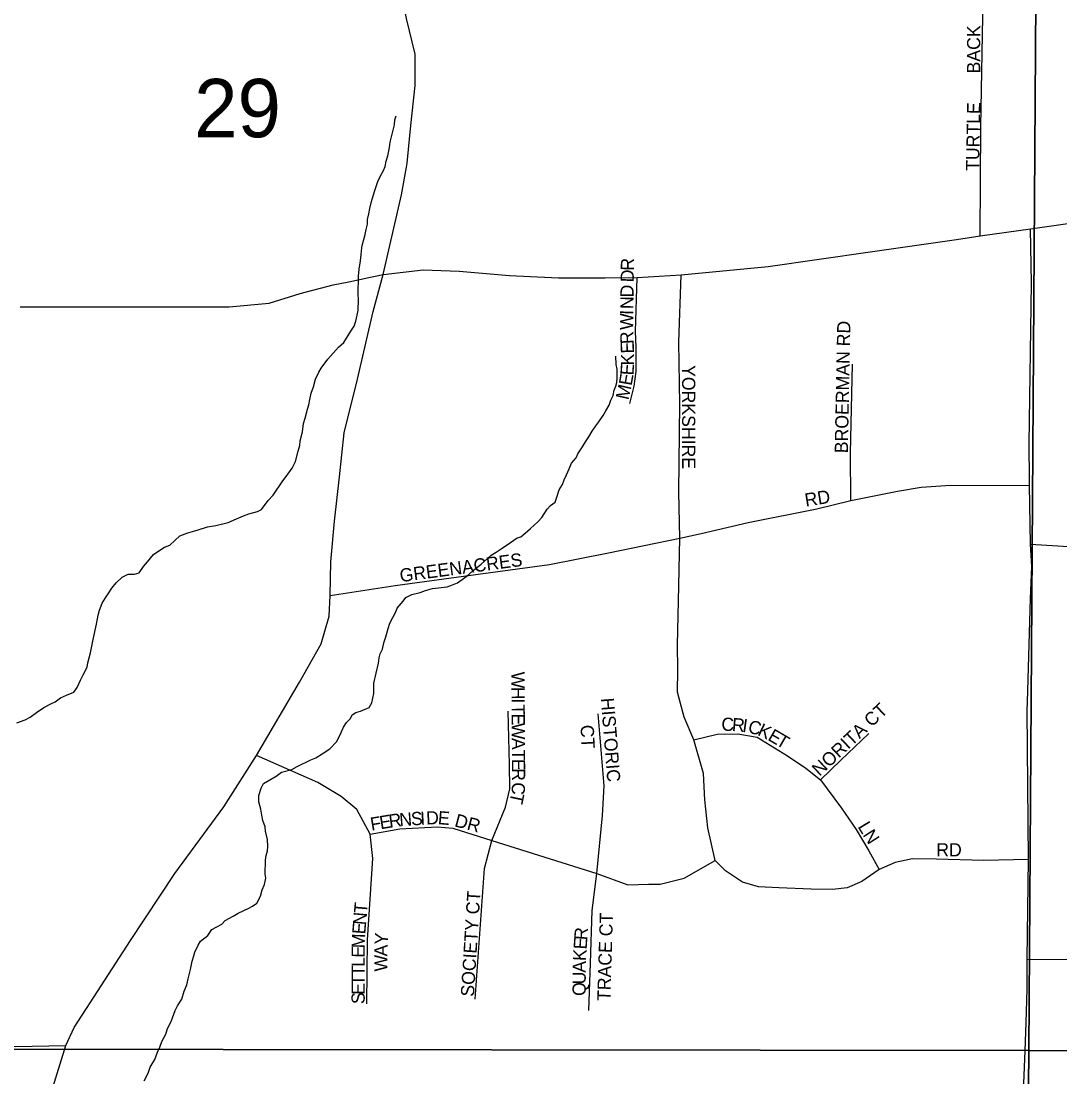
# Model space of a CAD drawing. Extents: x 8.5 to 81.5, y -1.2 to 22.4.
# Drawn here: x 50.481 to 51.227, y 16.747 to 17.505 of the extents above; entities that cross this region are included whole.
import ezdxf

# ---------------------------------------------------------------- set-up
doc = ezdxf.new("R2010")
doc.units = 0
for name, color, linetype in [('GM_X_County_Road', 7, 'Continuous'), ('GM_X_Minor_River', 7, 'Continuous'), ('GM_X_Section', 7, 'Continuous'), ('GM_X_Section_Text', 7, 'Continuous'), ('GM_X_Township_Road', 7, 'Continuous'), ('GM_X_Township_Subdivision', 7, 'Continuous'), ('GM_X_Township_Subdivision_Text', 7, 'Continuous')]:
    doc.layers.add(name, color=color, linetype=linetype)

msp = doc.modelspace()

# ---------------------------------------------------------------- linework, layer by layer
at = {"layer": 'GM_X_County_Road'}
for points in [[(50.75793, 17.4), (50.75844, 17.40285), (50.76108, 17.42986), (50.76428, 17.45862), (50.76428, 17.48098), (50.75788, 17.50651), (50.75149, 17.53845), (50.74191, 17.56721), (50.73232, 17.58957), (50.72912, 17.60234), (50.72592, 17.6247), (50.72591, 17.71909), (50.72849, 17.79691), (50.73133, 17.86836), (50.73141, 17.88387), (50.73142, 17.88479)], [(50.49923, 16.72358), (50.51345, 16.77007), (50.51949, 16.7828), (50.5311, 16.80062), (50.55984, 16.84532), (50.59179, 16.89324), (50.62693, 16.94116), (50.65036, 16.9779), (50.68124, 17.03061), (50.69667, 17.05814), (50.70241, 17.07801), (50.70332, 17.09279), (50.7036, 17.11685), (50.70624, 17.14597), (50.70983, 17.1778), (50.71317, 17.20946), (50.72275, 17.2478), (50.73417, 17.29633), (50.74119, 17.32303), (50.7544, 17.3802), (50.75793, 17.4)], [(50.74119, 17.32303), (50.77004, 17.32626), (50.79566, 17.32545), (50.8318, 17.32222), (50.86712, 17.3206), (50.90056, 17.3206), (50.92349, 17.32087), (50.95504, 17.32276), (51.0176, 17.32869), (51.09068, 17.33921), (51.15269, 17.34812), (51.16968, 17.35082), (51.20583, 17.35566), (51.2492, 17.36202), (51.32215, 17.37089), (51.39511, 17.38016), (51.46849, 17.39072), (51.50921, 17.39611), (51.56496, 17.39869), (51.66589, 17.39907)], [(50.48069, 17.29983), (50.63062, 17.29983), (50.65948, 17.30253), (50.68159, 17.30927), (50.70532, 17.31547), (50.71664, 17.31764), (50.73094, 17.32087), (50.74119, 17.32303)]]:
    msp.add_lwpolyline(points, dxfattribs=at)
at = {"layer": 'GM_X_Minor_River'}
for points in [[(50.74138, 17.39749), (50.74258, 17.40051), (50.74342, 17.40429), (50.74463, 17.40807), (50.7459, 17.41413), (50.74635, 17.41792), (50.74761, 17.42359), (50.74843, 17.42662), (50.74927, 17.4304), (50.74972, 17.43381), (50.75054, 17.43684)], [(50.75031, 17.43656), (50.75023, 17.43646)], [(50.47826, 17.00139), (50.48438, 17.00355), (50.48783, 17.00538), (50.49245, 17.00871), (50.49784, 17.01241), (50.50283, 17.01497), (50.50589, 17.01643), (50.50975, 17.01939), (50.51396, 17.02121), (50.51932, 17.02338), (50.52166, 17.02675), (50.52405, 17.03203), (50.52602, 17.03579), (50.52879, 17.04144), (50.52923, 17.04447), (50.53128, 17.05165), (50.53297, 17.05997), (50.53465, 17.06792), (50.53549, 17.07209), (50.53676, 17.07852), (50.5376, 17.08231), (50.5396, 17.08721), (50.54195, 17.09096), (50.54391, 17.09396), (50.54665, 17.09809), (50.54976, 17.10183), (50.55402, 17.10592), (50.55824, 17.10812), (50.56279, 17.10803), (50.56623, 17.1091), (50.56936, 17.1136), (50.57208, 17.11696), (50.57636, 17.1222), (50.58021, 17.12478), (50.58444, 17.12736), (50.58826, 17.1288), (50.59523, 17.13551), (50.60096, 17.13767), (50.6044, 17.13874), (50.6086, 17.1398), (50.61509, 17.14195), (50.62119, 17.14297), (50.62996, 17.14508), (50.63608, 17.14762), (50.64106, 17.1498), (50.64488, 17.15124), (50.65099, 17.15302), (50.65405, 17.15448), (50.65874, 17.16085), (50.66223, 17.16458), (50.66927, 17.17508), (50.67161, 17.17807), (50.67591, 17.18407), (50.67829, 17.18896), (50.68033, 17.19614), (50.68156, 17.2003), (50.68163, 17.20372), (50.68328, 17.21015), (50.68416, 17.21621), (50.68538, 17.21999), (50.68702, 17.22641), (50.68785, 17.22944), (50.68868, 17.23322), (50.68953, 17.23777), (50.69115, 17.24229), (50.69278, 17.24796), (50.69516, 17.25285), (50.69674, 17.25586), (50.70142, 17.26223), (50.70919, 17.27082), (50.71305, 17.27416), (50.71815, 17.28242), (50.7205, 17.2858), (50.72171, 17.28957), (50.72338, 17.29714), (50.72355, 17.30512), (50.72325, 17.30892), (50.72351, 17.32184), (50.72399, 17.32677), (50.72488, 17.33283), (50.72534, 17.33701), (50.72578, 17.34004), (50.72624, 17.34383), (50.72746, 17.34799), (50.7283, 17.35177), (50.72913, 17.35517), (50.72997, 17.35896), (50.73004, 17.36238), (50.73088, 17.36654), (50.73172, 17.37032), (50.73296, 17.37524), (50.73418, 17.37939), (50.73541, 17.38393), (50.73742, 17.38959), (50.73941, 17.39373), (50.74138, 17.39749)], [(50.65478, 16.93137), (50.6541, 16.93519), (50.65343, 16.93938), (50.65202, 16.94473), (50.65212, 16.94929), (50.65374, 16.95458), (50.65533, 16.95796), (50.66454, 16.9631), (50.6684, 16.96607), (50.67564, 16.96782), (50.67949, 16.97003), (50.68945, 16.97477), (50.69289, 16.97622), (50.69751, 16.97917), (50.70289, 16.98286), (50.70793, 16.98808), (50.7111, 16.99448), (50.7127, 16.99825), (50.71504, 17.00162), (50.71776, 17.00461), (50.71895, 17.00725), (50.72164, 17.00871), (50.72507, 17.00978), (50.7312, 17.01232), (50.73317, 17.01571), (50.73444, 17.02252), (50.73459, 17.02974), (50.73792, 17.04411), (50.73838, 17.04791), (50.7392, 17.05093), (50.74079, 17.05432), (50.74164, 17.05886), (50.74324, 17.06301), (50.74488, 17.06906), (50.7461, 17.07284), (50.75044, 17.08111), (50.75126, 17.08375), (50.75553, 17.08861), (50.75748, 17.09123), (50.7617, 17.09343), (50.7678, 17.09483), (50.77163, 17.09627), (50.77659, 17.09769), (50.78724, 17.099), (50.79106, 17.10045), (50.79451, 17.1019), (50.79797, 17.10411), (50.8026, 17.10782), (50.80607, 17.11079), (50.81148, 17.11524), (50.81611, 17.11933), (50.81882, 17.12156), (50.82228, 17.12377), (50.82651, 17.12672), (50.83267, 17.13078), (50.83729, 17.13411), (50.83996, 17.13482), (50.84305, 17.13742), (50.84691, 17.14076), (50.85232, 17.14559), (50.85504, 17.14858), (50.85895, 17.15458), (50.86129, 17.1572), (50.86475, 17.15979), (50.86557, 17.16243), (50.86759, 17.16847), (50.86994, 17.17223), (50.87115, 17.17562), (50.87275, 17.17939), (50.87473, 17.18353), (50.87633, 17.18768), (50.87982, 17.19141), (50.88102, 17.19443), (50.88416, 17.19931), (50.88651, 17.20306), (50.88886, 17.20643), (50.89122, 17.21057), (50.89395, 17.21431), (50.89591, 17.21731), (50.89904, 17.22181), (50.90101, 17.2252), (50.90337, 17.22933), (50.90458, 17.23273), (50.90616, 17.23611), (50.907, 17.2399), (50.9082, 17.24292), (50.90901, 17.24556), (50.90908, 17.2486), (50.90921, 17.25506), (50.90852, 17.25849), (50.90809, 17.26431)], [(50.56975, 16.74455), (50.57252, 16.7502), (50.57412, 16.75435), (50.57728, 16.75999), (50.57847, 16.76262), (50.57928, 16.76527), (50.58087, 16.76866), (50.58247, 16.77281), (50.58524, 16.77807), (50.58646, 16.78223), (50.58921, 16.78711), (50.59203, 16.79504), (50.59362, 16.79843), (50.59676, 16.80331), (50.59839, 16.80898), (50.60038, 16.8135), (50.60123, 16.81766), (50.60288, 16.82447), (50.60415, 16.83052), (50.60536, 16.8343), (50.60618, 16.83694), (50.60855, 16.84184), (50.61013, 16.84485), (50.61553, 16.84892), (50.61827, 16.85305), (50.62556, 16.85708), (50.62789, 16.8597), (50.63364, 16.86262), (50.6371, 16.86483), (50.64477, 16.86848), (50.64745, 16.86995), (50.65053, 16.87217), (50.65329, 16.87705), (50.65452, 16.88159), (50.65612, 16.88536), (50.65697, 16.8899), (50.65665, 16.89295), (50.65685, 16.90283), (50.65731, 16.90624), (50.65813, 16.90964), (50.65858, 16.91267), (50.6583, 16.91762), (50.6569, 16.92373), (50.65659, 16.92678), (50.65478, 16.93137)]]:
    msp.add_lwpolyline(points, dxfattribs=at)
at = {"layer": 'GM_X_Section'}
for points in [[(50.25023, 17.8478), (51.21175, 17.84266), (51.20445, 16.76644), (50.24059, 16.76746)], [(51.21175, 17.84266), (52.21491, 17.8371), (52.20343, 16.76022), (51.20445, 16.76644)], [(50.24059, 16.76746), (51.20445, 16.76644), (51.19552, 15.7645), (50.22978, 15.76592)], [(51.20445, 16.76644), (52.20343, 16.76022), (52.20331, 15.76418), (51.19552, 15.7645)]]:
    msp.add_lwpolyline(points, close=True, dxfattribs=at)
at = {"layer": 'GM_X_Township_Road'}
for points in [[(51.20499, 17.17592), (51.2048, 17.20162), (51.20656, 17.31667), (51.20583, 17.35566)], [(51.20603, 17.09606), (51.20658, 17.11354), (51.20576, 17.12959), (51.20502, 17.17189), (51.20499, 17.17592)], [(51.20353, 17.01621), (51.20585, 17.09049), (51.20603, 17.09606)], [(51.20251, 16.78655), (51.20336, 16.81046), (51.20344, 16.83199), (51.20438, 16.90328), (51.20334, 17.01035), (51.20353, 17.01621)], [(51.19915, 16.47701), (51.19938, 16.50285), (51.20017, 16.55957), (51.20016, 16.62932), (51.20016, 16.69532), (51.20015, 16.72016), (51.20054, 16.73105), (51.20179, 16.76622), (51.20251, 16.78655)], [(49.64777, 16.76678), (49.71334, 16.76585), (49.83755, 16.76604), (49.97831, 16.76789), (50.07202, 16.76861), (50.15796, 16.76938), (50.26884, 16.76697), (50.39441, 16.76952), (50.47721, 16.76928), (50.51345, 16.77007)]]:
    msp.add_lwpolyline(points, dxfattribs=at)
at = {"layer": 'GM_X_Township_Subdivision'}
for points in [[(51.16968, 17.35082), (51.17006, 17.42919), (51.17161, 17.50793), (51.17161, 17.5199), (51.17161, 17.55155), (51.16929, 17.57471), (51.16698, 17.589), (51.15964, 17.61794)], [(50.9183, 17.23043), (50.92146, 17.24299), (50.92276, 17.25341), (50.92276, 17.25899), (50.92276, 17.2709), (50.92239, 17.28207), (50.92349, 17.32087)], [(51.20438, 16.90328), (51.1719, 16.90272), (51.13826, 16.9037), (51.12114, 16.90391), (51.10865, 16.90116), (51.09723, 16.89609), (51.08475, 16.88752), (51.07427, 16.88297), (51.06359, 16.88191), (51.04836, 16.88212), (51.02509, 16.88297), (51.0106, 16.88381), (50.99917, 16.8872), (50.9868, 16.89524), (50.97954, 16.90269), (50.97432, 16.92602), (50.97211, 16.94619), (50.97113, 16.96499), (50.96409, 16.98917), (50.95728, 17.00553), (50.95233, 17.02332), (50.95274, 17.03931), (50.95232, 17.05729), (50.95316, 17.0886), (50.95401, 17.13387), (50.95337, 17.16709), (50.95401, 17.22991), (50.95329, 17.27445), (50.95504, 17.32276)], [(51.07692, 17.1609), (51.0765, 17.19485), (51.07791, 17.25863)], [(50.70332, 17.09279), (50.74979, 17.10002), (50.80938, 17.10792), (50.8605, 17.11504), (50.90302, 17.12329), (50.95401, 17.13387), (50.96935, 17.13725), (51.0032, 17.14519), (51.05243, 17.15481), (51.07692, 17.1609), (51.11024, 17.16766), (51.12738, 17.17042), (51.14504, 17.17168), (51.20502, 17.17189)], [(51.20576, 17.12959), (51.28803, 17.12462)], [(50.81929, 16.91711), (50.82901, 16.94088), (50.83212, 16.95404), (50.83184, 16.97163), (50.83087, 17.00975)], [(50.89458, 16.89325), (50.89865, 16.93489), (50.89985, 16.95619), (50.89553, 17.00782)], [(50.96409, 16.98917), (50.98088, 16.99319), (50.99568, 16.99361), (51.00964, 16.99107), (51.03144, 16.97775), (51.04455, 16.96886), (51.05497, 16.96042), (51.07002, 16.94027), (51.08073, 16.92486), (51.08982, 16.90962), (51.09723, 16.89609)], [(51.05497, 16.96042), (51.06973, 16.97457), (51.08981, 16.99367)], [(50.72954, 16.79985), (50.73003, 16.84569), (50.73389, 16.90408), (50.73195, 16.92145), (50.7223, 16.9393), (50.71121, 16.94847), (50.69432, 16.9586), (50.65036, 16.9779)], [(50.73195, 16.92145), (50.75319, 16.92531), (50.78021, 16.92676), (50.79131, 16.92579), (50.81929, 16.91711), (50.89458, 16.89325), (50.91676, 16.88526), (50.93174, 16.88557)], [(50.80723, 16.80323), (50.81399, 16.89684), (50.81929, 16.91711)], [(50.93174, 16.88557), (50.93993, 16.88574), (50.95729, 16.89008), (50.97954, 16.90269)], [(50.88884, 16.79513), (50.89004, 16.82912), (50.89123, 16.86668), (50.89458, 16.89325)], [(51.20344, 16.83199), (51.24161, 16.83167), (51.26541, 16.83146), (51.27293, 16.83146)]]:
    msp.add_lwpolyline(points, dxfattribs=at)

# ---------------------------------------------------------------- texts
at = {"layer": 'GM_X_Section_Text'}
msp.add_text('29', height=0.041856, rotation=0.00001, dxfattribs=at).set_placement((50.60562, 17.42139))
at = {"layer": 'GM_X_Township_Subdivision_Text'}
for s, height, rotation, p in [('BACK', 0.00947, 90, (51.16967, 17.46717)), ('TURTLE', 0.00947, 88.91961, (51.16884, 17.3972)), ('R', 0.00947, 89.12569, (50.92118, 17.32565)), ('D', 0.00947, 89.12565, (50.92105, 17.31732)), ('D', 0.00947, 89.10379, (50.92088, 17.30647)), ('N', 0.00947, 89.12565, (50.92076, 17.29814)), ('I', 0.00947, 89.12598, (50.92069, 17.29398)), ('W', 0.00947, 89.52926, (50.9206, 17.28316)), ('BROERMAN RD', 0.0094697, 88.87514, (51.07467, 17.1947)), ('R', 0.00947, 93.04421, (50.92109, 17.27333)), ('E', 0.00947, 91.7337, (50.9213, 17.26643)), ('K', 0.00947, 89.83233, (50.92128, 17.25776)), ('E', 0.00947, 85.96336, (50.92079, 17.25042)), ('E', 0.00947, 80.17617, (50.91953, 17.24284)), ('YORKSHIRE', 0.00947, 270, (50.95574, 17.258)), ('M', 0.00947, 77.27162, (50.91722, 17.23258)), ('RD', 0.00947, 8.96731, (51.04451, 17.15643)), ('GREENACRES', 0.00947, 7.59528, (50.75372, 17.10227)), ('W', 0.00947, 270.36987, (50.83324, 17.03803)), ('H', 0.00947, 270.36454, (50.83331, 17.0272)), ('I', 0.00947, 270.36163, (50.83336, 17.01886)), ('HISTORIC', 0.00947, 274.46818, (50.8974, 17.01897)), ('NORITA CT', 0.00947, 43.36401, (51.0544, 16.96264)), ('T', 0.00947, 270.3552, (50.83339, 17.0147)), ('E', 0.00947, 270.37193, (50.83343, 17.00803)), ('W', 0.00947, 270.36987, (50.83348, 17.00136)), ('C', 0.00947, 359.75712, (50.98394, 16.99562)), ('R', 0.00947, 355.13754, (50.99124, 16.99559)), ('I', 0.00947, 351.7957, (50.99857, 16.99498)), ('C', 0.00947, 346.79424, (51.00248, 16.99442)), ('K', 0.00947, 334.51975, (51.00927, 16.99289)), ('CT', 0.00947, 273.17782, (50.8828, 16.9997)), ('E', 0.00947, 329.86548, (51.01662, 16.98939)), ('T', 0.00947, 329.7298, (51.02238, 16.98605)), ('A', 0.00947, 270.36454, (50.83355, 16.99053)), ('T', 0.00947, 270.36038, (50.8336, 16.9822)), ('E', 0.00947, 270.37193, (50.83364, 16.97553)), ('R', 0.00947, 270.36433, (50.83368, 16.96887)), ('C', 0.00947, 266.89021, (50.83375, 16.95902)), ('T', 0.00947, 258.2239, (50.83339, 16.95191)), ('F', 0.00947, 9.38596, (50.73282, 16.92393)), ('E', 0.00947, 9.359, (50.7394, 16.92501)), ('R', 0.00947, 8.31217, (50.74593, 16.92609)), ('N', 0.00947, 4.41882, (50.75318, 16.92715)), ('S', 0.00947, 3.33438, (50.76145, 16.92779)), ('I', 0.00947, 3.32537, (50.7681, 16.92818)), ('D', 0.00947, 2.16396, (50.77221, 16.92842)), ('E', 0.00947, 355.5154, (50.78025, 16.92874)), ('DR', 0.00947, 345.25417, (50.79191, 16.92722)), ('L', 0.00947, 301.34798, (51.08148, 16.92695)), ('N', 0.00947, 302.64224, (51.08507, 16.92106)), ('RD', 0.00947, 0.00001, (51.13812, 16.90561)), ('SOCIETY CT', 0.00947, 86.42297, (50.80634, 16.80478)), ('T', 0.00947, 85.07523, (50.72962, 16.86439)), ('N', 0.00947, 85.09841, (50.72891, 16.85609)), ('TRACE CT', 0.00947, 88.29105, (50.90429, 16.80174)), ('E', 0.00947, 85.26811, (50.72836, 16.84945)), ('M', 0.00947, 88.06899, (50.72803, 16.83958)), ('Y', 0.00947, 86.41275, (50.74442, 16.84201)), ('R', 0.00947, 86.16007, (50.88768, 16.8453)), ('A', 0.00947, 89.23492, (50.74431, 16.8338)), ('E', 0.00947, 86.22771, (50.88724, 16.83865)), ('E', 0.00947, 89.94534, (50.72802, 16.83299)), ('W', 0.00947, 89.93274, (50.7443, 16.823)), ('K', 0.00947, 86.785, (50.88677, 16.83036)), ('L', 0.00947, 89.97267, (50.72802, 16.82633)), ('T', 0.00947, 89.95718, (50.72802, 16.81966)), ('A', 0.00947, 88.84155, (50.88661, 16.82211)), ('T', 0.00947, 89.97267, (50.72801, 16.813)), ('U', 0.00947, 89.93441, (50.8866, 16.81383)), ('E', 0.00947, 89.97066, (50.72801, 16.80633)), ('Q', 0.00947, 89.93441, (50.88659, 16.8055)), ('S', 0.00947, 89.97267, (50.72801, 16.79967))]:
    msp.add_text(s, height=height, rotation=rotation, dxfattribs=at).set_placement(p)

doc.saveas('drawing.dxf')
